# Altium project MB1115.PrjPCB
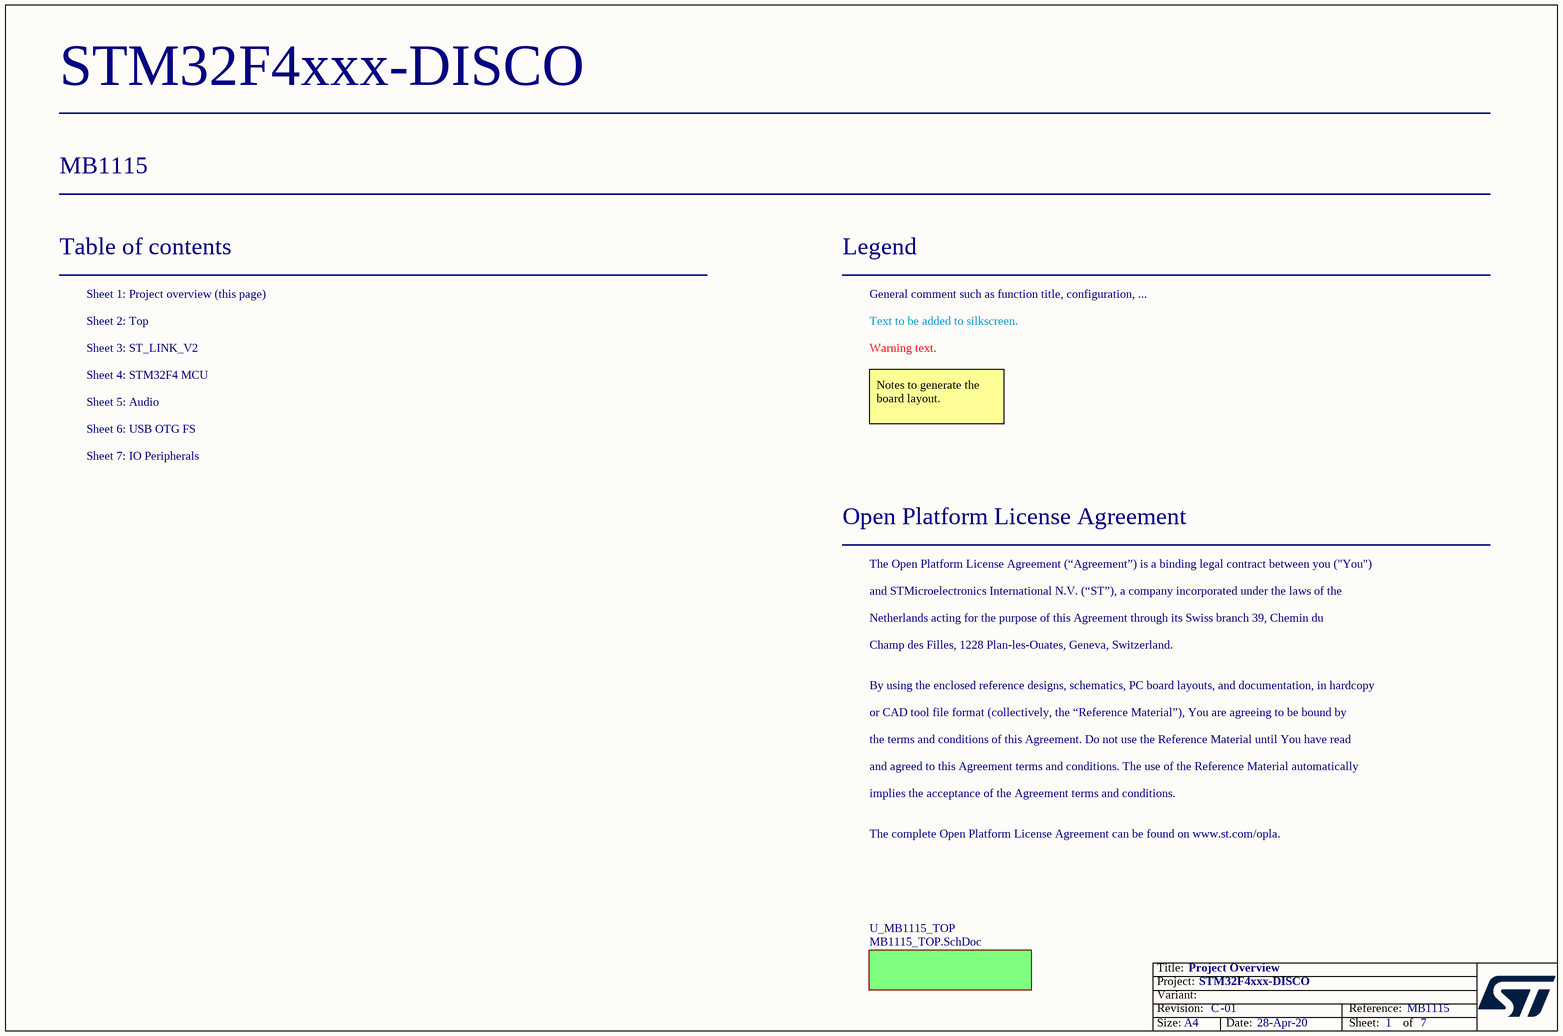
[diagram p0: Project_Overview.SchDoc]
Board_Reference: MB1115; Board_PCB_Revision: C; Board_Name: STM32F4xxx-DISCO; Board_Document_Date: 28-Apr-20; Board_Assembly_Revision: 01
7 sheets, 197 parts. Net scope: flat (ports and power ports of the same name join across sheets).
Board file: MB1115C.PcbDoc
Sheets:
  Project_Overview.SchDoc
    U_MB1115_TOP = MB1115_TOP.SchDoc
      U_ST_LINK = ST_LINK_V2.SCHDOC
      U_Audio = Audio.SchDoc
      U_IO Peripherals = IO Peripherals.SchDoc
      U_STM32Fx = STM32Fx.SchDoc
      U_USB_OTG_FS = USB_OTG_FS.SchDoc

## Sheet Project_Overview.SchDoc: Project Overview
size A4; Date: Not used; ApprovedBy: Not used; CheckedBy: Not used; Author: Not used; CompanyName: STMicroelectronics; DrawnBy: Not used; Engineer: Not used; Organization: Not used; Address1: Not used; Address2: Not used; Address3: Not used; Address4: Not used; DocumentNumber: Not used; Revision: Not used; SheetNumber: 1; SheetTotal: 7

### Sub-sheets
U_MB1115_TOP = MB1115_TOP.SchDoc: no entries

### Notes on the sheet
- Table of contents
- Sheet 1: Project overview (this page)
- Legend
- General comment such as function title, configuration, ...
- Sheet 2: Top
- Sheet 3: ST_LINK_V2
- Sheet 4: STM32F4 MCU
- Text to be added to silkscreen.
- Warning text.
- Sheet 6: USB OTG FS
- Sheet 5: Audio
- Notes to generate the board layout.
- Sheet 7: IO Peripherals
- Open Platform License Agreement
- The Open Platform License Agreement (“Agreement”) is a binding legal contract between you ("You")
- and STMicroelectronics International N.V. (“ST”), a company incorporated under the laws of the
- Netherlands acting for the purpose of this Agreement through its Swiss branch 39, Chemin du
- Champ des Filles, 1228 Plan-les-Ouates, Geneva, Switzerland.
- By using the enclosed reference designs, schematics, PC board layouts, and documentation, in hardcopy
- or CAD tool file format (collectively, the “Reference Material”), You are agreeing to be bound by
- the terms and conditions of this Agreement. Do not use the Reference Material until You have read
- and agreed to this Agreement terms and conditions. The use of the Reference Material automatically
- implies the acceptance of the Agreement terms and conditions.
- The complete Open Platform License Agreement can be found on www.st.com/opla.

## Sheet MB1115_TOP.SchDoc: TOP
size A4; DocumentNumber: 1; SheetNumber: 2; SheetTotal: 7; PageSetup: Record=PageOptions¦CenterHorizontal=True¦CenterVertical=True¦PrintScale=1.00¦XCorrection=1.00¦YCorrection=1.00¦PrintKind=1¦BorderSize=5000000¦LeftOffset=0¦BottomOffset=0¦Orientation=2¦PaperLength=1000¦PaperWidth=1000¦Scale=100¦PaperSource=15¦PrintQuality=1200¦MediaType=1¦DitherType=10¦PaperKind=A4¦PrintScaleMode=1
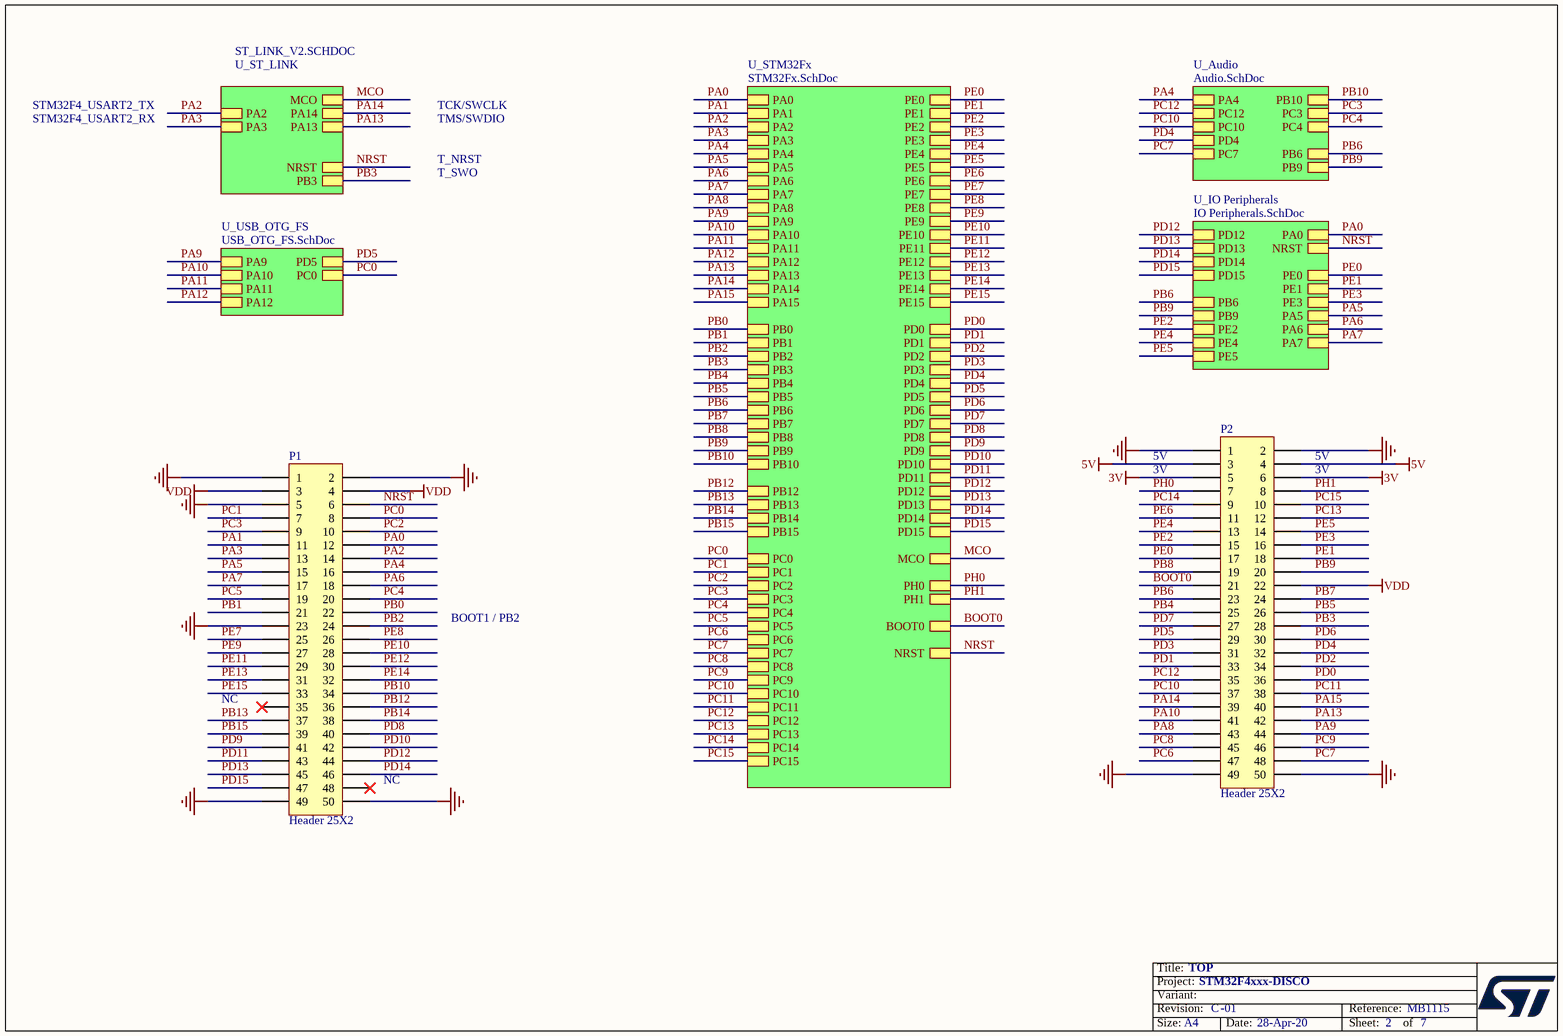
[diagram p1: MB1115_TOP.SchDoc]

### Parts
P1  Header 25X2  [HDR2X25 (Primary)]
P2  Header 25X2  [HDR2X25 (Primary)]

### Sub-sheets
U_Audio = Audio.SchDoc: PA4, PC12, PC10, PD4, PC7, PC3, PB10, PC4, PB6, PB9
U_IO Peripherals = IO Peripherals.SchDoc: PA0, NRST, PE0, PE1, PE3, PA5, PA7, PA6, PE4, PE5, PE2, PB6, PB9, PD12, PD13, PD14, PD15
U_ST_LINK = ST_LINK_V2.SCHDOC: PA13, PA14, NRST, PB3, MCO, PA3, PA2
U_STM32Fx = STM32Fx.SchDoc: PD2, BOOT0, PH1, PH0, NRST, PE0, PE1, PE2, PE3, PE4, PE5, PE6, PE7, PE8, PE9, PE10, PE11, PE12, PE13, PE14, PE15, PD0, PD1, PD3, PD4, PD5, PD6, PD7, PD8, PD9, PD10, PD11, PD12, PD13, PD14, PD15, MCO, PA1, PA2, PA3, PA4, PA5, PA6, PA7, PA8, PA9, PA10, PA11, PA12, PA13, PA14, PA15, PB1, PB2, PB3, PB4, PB5, PB6, PB7, PB8, PB9, PB10, PB12, PB13, PB14, PB15, PC1, PC2, PC3, PC4, PC5, PC6, PC7, PC8, PC9, PC10, PC11, PC12, PC13, PA0, PB0, PC0, PC14, PC15
U_USB_OTG_FS = USB_OTG_FS.SchDoc: PC0, PD5, PA9, PA10, PA11, PA12

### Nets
3V: P2.5 P2.6
5V: P2.3 P2.4
GND: P1.1 P1.2 P1.5 P1.23 P1.49 P1.50 P2.1 P2.2 P2.49 P2.50
VDD: P1.3 P1.4 P2.22
BOOT0: P2.21 ; sheet U_STM32Fx/BOOT0
MCO: sheet U_ST_LINK/MCO, sheet U_STM32Fx/MCO
NRST: P1.6 ; sheet U_ST_LINK/NRST, sheet U_IO Peripherals/NRST, sheet U_STM32Fx/NRST
PA0: P1.12 ; sheet U_IO Peripherals/PA0, sheet U_STM32Fx/PA0
PA1: P1.11 ; sheet U_STM32Fx/PA1
PA2: P1.14 ; sheet U_ST_LINK/PA2, sheet U_STM32Fx/PA2
PA3: P1.13 ; sheet U_ST_LINK/PA3, sheet U_STM32Fx/PA3
PA4: P1.16 ; sheet U_Audio/PA4, sheet U_STM32Fx/PA4
PA5: P1.15 ; sheet U_IO Peripherals/PA5, sheet U_STM32Fx/PA5
PA6: P1.18 ; sheet U_IO Peripherals/PA6, sheet U_STM32Fx/PA6
PA7: P1.17 ; sheet U_IO Peripherals/PA7, sheet U_STM32Fx/PA7
PA8: P2.43 ; sheet U_STM32Fx/PA8
PA9: P2.44 ; sheet U_STM32Fx/PA9, sheet U_USB_OTG_FS/PA9
PA10: P2.41 ; sheet U_STM32Fx/PA10, sheet U_USB_OTG_FS/PA10
PA11: sheet U_STM32Fx/PA11, sheet U_USB_OTG_FS/PA11
PA12: sheet U_STM32Fx/PA12, sheet U_USB_OTG_FS/PA12
PA13: P2.42 ; sheet U_ST_LINK/PA13, sheet U_STM32Fx/PA13
PA14: P2.39 ; sheet U_ST_LINK/PA14, sheet U_STM32Fx/PA14
PA15: P2.40 ; sheet U_STM32Fx/PA15
PB0: P1.22 ; sheet U_STM32Fx/PB0
PB1: P1.21 ; sheet U_STM32Fx/PB1
PB2: P1.24 ; sheet U_STM32Fx/PB2
PB3: P2.28 ; sheet U_ST_LINK/PB3, sheet U_STM32Fx/PB3
PB4: P2.25 ; sheet U_STM32Fx/PB4
PB5: P2.26 ; sheet U_STM32Fx/PB5
PB6: P2.23 ; sheet U_Audio/PB6, sheet U_IO Peripherals/PB6, sheet U_STM32Fx/PB6
PB7: P2.24 ; sheet U_STM32Fx/PB7
PB8: P2.19 ; sheet U_STM32Fx/PB8
PB9: P2.20 ; sheet U_Audio/PB9, sheet U_IO Peripherals/PB9, sheet U_STM32Fx/PB9
PB10: P1.34 ; sheet U_Audio/PB10, sheet U_STM32Fx/PB10
PB12: P1.36 ; sheet U_STM32Fx/PB12
PB13: P1.37 ; sheet U_STM32Fx/PB13
PB14: P1.38 ; sheet U_STM32Fx/PB14
PB15: P1.39 ; sheet U_STM32Fx/PB15
PC0: P1.8 ; sheet U_STM32Fx/PC0, sheet U_USB_OTG_FS/PC0
PC1: P1.7 ; sheet U_STM32Fx/PC1
PC2: P1.10 ; sheet U_STM32Fx/PC2
PC3: P1.9 ; sheet U_Audio/PC3, sheet U_STM32Fx/PC3
PC4: P1.20 ; sheet U_Audio/PC4, sheet U_STM32Fx/PC4
PC5: P1.19 ; sheet U_STM32Fx/PC5
PC6: P2.47 ; sheet U_STM32Fx/PC6
PC7: P2.48 ; sheet U_Audio/PC7, sheet U_STM32Fx/PC7
PC8: P2.45 ; sheet U_STM32Fx/PC8
PC9: P2.46 ; sheet U_STM32Fx/PC9
PC10: P2.37 ; sheet U_Audio/PC10, sheet U_STM32Fx/PC10
PC11: P2.38 ; sheet U_STM32Fx/PC11
PC12: P2.35 ; sheet U_Audio/PC12, sheet U_STM32Fx/PC12
PC13: P2.12 ; sheet U_STM32Fx/PC13
PC14: P2.9 ; sheet U_STM32Fx/PC14
PC15: P2.10 ; sheet U_STM32Fx/PC15
PD0: P2.36 ; sheet U_STM32Fx/PD0
PD1: P2.33 ; sheet U_STM32Fx/PD1
PD2: P2.34 ; sheet U_STM32Fx/PD2
PD3: P2.31 ; sheet U_STM32Fx/PD3
PD4: P2.32 ; sheet U_Audio/PD4, sheet U_STM32Fx/PD4
PD5: P2.29 ; sheet U_STM32Fx/PD5, sheet U_USB_OTG_FS/PD5
PD6: P2.30 ; sheet U_STM32Fx/PD6
PD7: P2.27 ; sheet U_STM32Fx/PD7
PD8: P1.40 ; sheet U_STM32Fx/PD8
PD9: P1.41 ; sheet U_STM32Fx/PD9
PD10: P1.42 ; sheet U_STM32Fx/PD10
PD11: P1.43 ; sheet U_STM32Fx/PD11
PD12: P1.44 ; sheet U_IO Peripherals/PD12, sheet U_STM32Fx/PD12
PD13: P1.45 ; sheet U_IO Peripherals/PD13, sheet U_STM32Fx/PD13
PD14: P1.46 ; sheet U_IO Peripherals/PD14, sheet U_STM32Fx/PD14
PD15: P1.47 ; sheet U_IO Peripherals/PD15, sheet U_STM32Fx/PD15
PE0: P2.17 ; sheet U_IO Peripherals/PE0, sheet U_STM32Fx/PE0
PE1: P2.18 ; sheet U_IO Peripherals/PE1, sheet U_STM32Fx/PE1
PE2: P2.15 ; sheet U_IO Peripherals/PE2, sheet U_STM32Fx/PE2
PE3: P2.16 ; sheet U_IO Peripherals/PE3, sheet U_STM32Fx/PE3
PE4: P2.13 ; sheet U_IO Peripherals/PE4, sheet U_STM32Fx/PE4
PE5: P2.14 ; sheet U_IO Peripherals/PE5, sheet U_STM32Fx/PE5
PE6: P2.11 ; sheet U_STM32Fx/PE6
PE7: P1.25 ; sheet U_STM32Fx/PE7
PE8: P1.26 ; sheet U_STM32Fx/PE8
PE9: P1.27 ; sheet U_STM32Fx/PE9
PE10: P1.28 ; sheet U_STM32Fx/PE10
PE11: P1.29 ; sheet U_STM32Fx/PE11
PE12: P1.30 ; sheet U_STM32Fx/PE12
PE13: P1.31 ; sheet U_STM32Fx/PE13
PE14: P1.32 ; sheet U_STM32Fx/PE14
PE15: P1.33 ; sheet U_STM32Fx/PE15
PH0: P2.7 ; sheet U_STM32Fx/PH0
PH1: P2.8 ; sheet U_STM32Fx/PH1

Not connected (* = marked no-connect by the designer): P1 35* 48*

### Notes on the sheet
- STM32F4_USART2_TX
- TCK/SWCLK
- STM32F4_USART2_RX
- TMS/SWDIO
- T_SWO
- T_NRST
- 5V
- 3V
- (near P2) 5V
- (near P2) 3V
- BOOT1 / PB2
- NC
- (near P1) NC

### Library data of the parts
P1 P2 = Header 25X2: Header, 25-Pin, Dual row

## Sheet ST_LINK_V2.SCHDOC: ST-LINK/V2 (SWD only)
size A4; DocumentNumber: 2; SheetNumber: 3; SheetTotal: 7
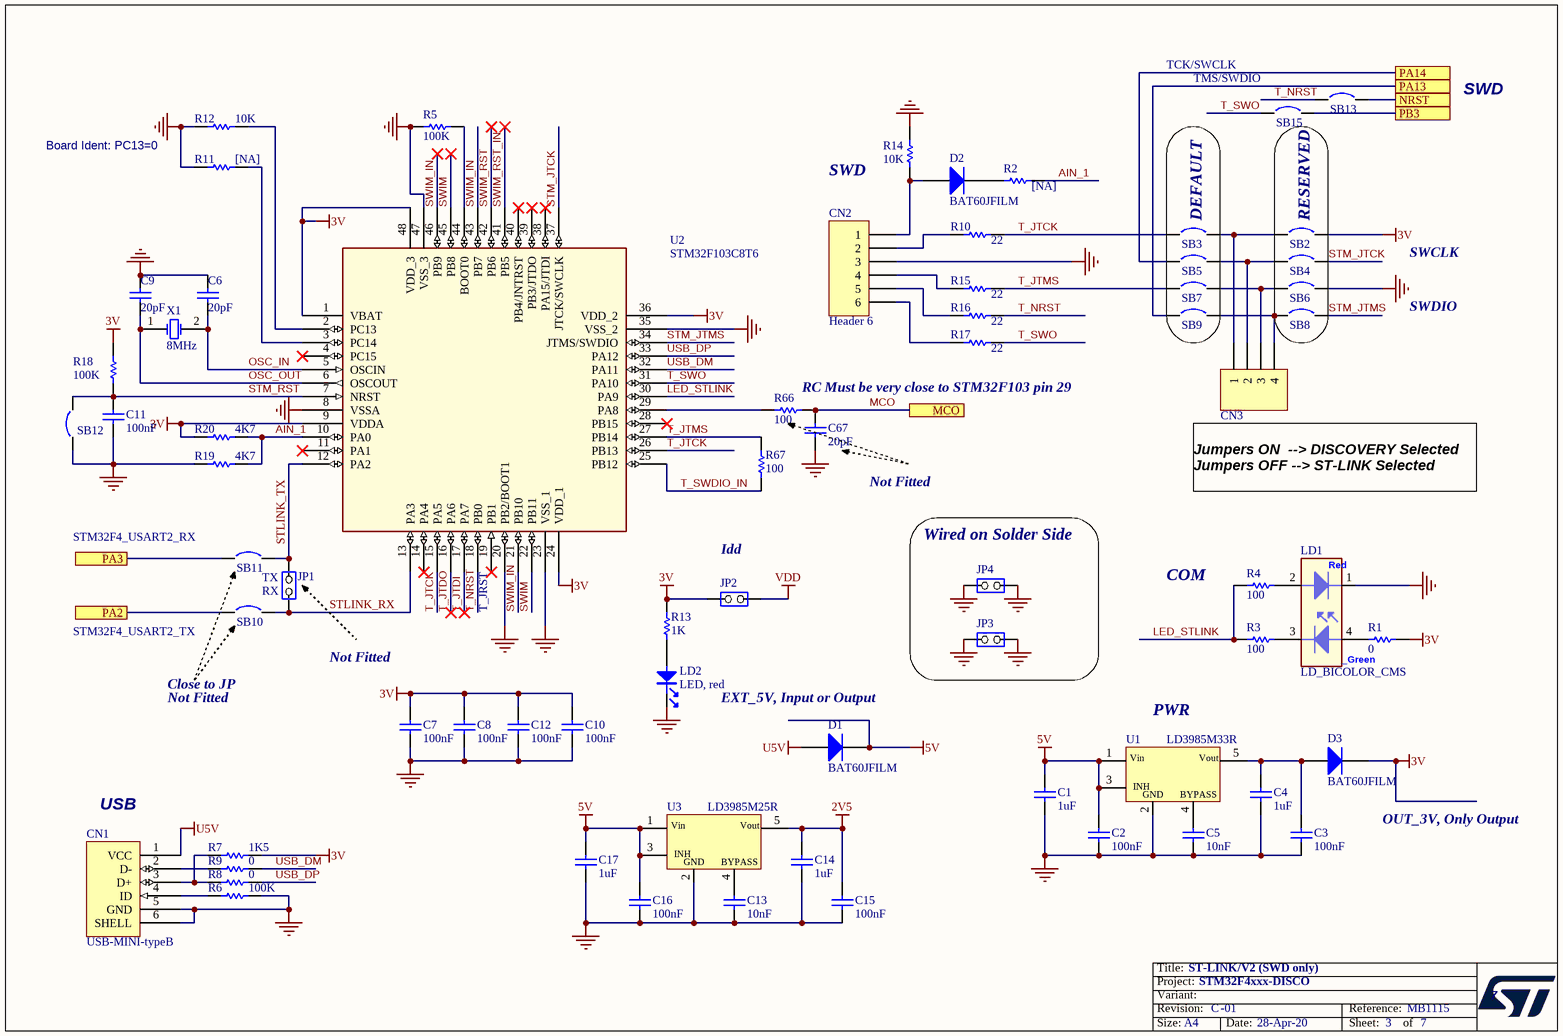
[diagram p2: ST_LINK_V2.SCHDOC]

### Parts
C1  1uF  [0603C (Primary)]
C2  100nF  [0402C (Primary)]
C3  100nF  [0402C (Primary)]
C4  1uF  [0603C (Primary)]
C5  10nF  [0603C (Primary)]
C6  20pF  [0402C (Primary)]
C7  100nF  [0402C (Primary)]
C8  100nF  [0402C (Primary)]
C9  20pF  [0402C (Primary)]
C10  100nF  [0402C (Primary)]
C11  100nF  [0402C (Primary)]
C12  100nF  [0402C (Primary)]
C13  10nF  [0603C (Primary)]
C14  1uF  [0603C (Primary)]
C15  100nF  [0402C (Primary)]
C16  100nF  [0402C (Primary)]
C17  1uF  [0603C (Primary)]
C67  20pF  [0402C (Primary)]
CN1  USB-MINI-typeB  [USB-MINI-B-SMD (Primary)]
CN2  Header 6  [HDR1X6 (Primary)]
CN3  Header 4  [Header 4 (Primary)]  (value not drawn)
D1  BAT60JFILM  [SOD323/A (Primary)]
D2  BAT60JFILM  [SOD323/A (Primary)]
D3  BAT60JFILM  [SOD323/A (Primary)]
JP1  JP2  [SIP2/2.54 (Primary)]  (value not drawn)
JP2  (no value)  [SIP2/2.54 (Primary)]
JP3  (no value)  [SIP2/2.54 (Primary)]
JP4  (no value)  [SIP2/2.54 (Primary)]
LD1  LD_BICOLOR_CMS  [HSMF-A201 (Primary)]
LD2  LED, red  [0603D (Primary)]
R1  0  [0402R (Primary)]
R2  [NA]  [0402R (Primary)]
R3  100  [0402R (Primary)]
R4  100  [0402R (Primary)]
R5  100K  [0402R (Primary)]
R6  100K  [0402R (Primary)]
R7  1K5  [0402R (Primary)]
R8  0  [0402R (Primary)]
R9  0  [0402R (Primary)]
R10  22  [0402R (Primary)]
R11  [NA]  [0402R (Primary)]
R12  10K  [0402R (Primary)]
R13  1K  [0402R (Primary)]
R14  10K  [0402R (Primary)]
R15  22  [0402R (Primary)]
R16  22  [0402R (Primary)]
R17  22  [0402R (Primary)]
R18  100K  [0402R (Primary)]
R19  4K7  [0402R (Primary)]
R20  4K7  [0402R (Primary)]
R66  100  [0402R (Primary)]
R67  100  [0402R (Primary)]
SB2  Circuit Breaker  [JP2_SMD (Primary)]  (value not drawn)
SB3  Circuit Breaker  [JP2_SMD (Primary)]  (value not drawn)
SB4  Circuit Breaker  [JP2_SMD (Primary)]  (value not drawn)
SB5  Circuit Breaker  [JP2_SMD (Primary)]  (value not drawn)
SB6  Circuit Breaker  [JP2_SMD (Primary)]  (value not drawn)
SB7  Circuit Breaker  [JP2_SMD (Primary)]  (value not drawn)
SB8  Circuit Breaker  [JP2_SMD (Primary)]  (value not drawn)
SB9  Circuit Breaker  [JP2_SMD (Primary)]  (value not drawn)
SB10  Circuit Breaker  [JP2_SMD (Primary)]  (value not drawn)
SB11  Circuit Breaker  [JP2_SMD (Primary)]  (value not drawn)
SB12  Circuit Breaker  [JP2_SMD (Primary)]  (value not drawn)
SB13  Circuit Breaker  [JP2_SMD (Primary)]  (value not drawn)
SB15  Circuit Breaker  [JP2_SMD (Primary)]  (value not drawn)
U1  LD3985M33R  [SOT-23-5L (Primary)]
U2  STM32F103C8T6  [LQFP48 (Primary)]
U3  LD3985M25R  [SOT-23-5L (Primary)]
X1  8MHz  [XTAL1 (Primary)]

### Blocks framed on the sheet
DEFAULT: SB3 SB5 SB7 SB9
RESERVED: SB2 SB4 SB6 SB8
Wired on Solder Side: JP3 JP4

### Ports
MCO, NRST, PA2, PA3, PA13, PA14, PB3

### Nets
2V5: C14.1 C15.2 U3.5(Vout)
3V: C7.2 C8.2 C10.2 C12.1 D3.2(K) JP2.1(COMMON) R1.2 R7.2 R13.2 R18.2 R20.1 SB2.2 U2.1(VBAT) U2.9(VDDA) U2.24(VDD_1) U2.36(VDD_2) U2.48(VDD_3)
5V: C1.2 C2.2 C16.2 C17.2 D1.2(K) U1.1(Vin) U1.3(CE) U3.1(Vin) U3.3(CE)
GND: C1.1 C2.1 C3.1 C4.2 C5.1 C6.1 C7.1 C8.1 C9.1 C10.1 C11.1 C12.2 C13.1 C14.2 C15.1 C16.1 C17.1 C67.2 CN1.5(GND) CN1.6(SHELL) CN2.3 JP3.1(COMMON) JP3.2(NO) JP4.1(COMMON) JP4.2(NO) LD1.1 LD2.2 R5.1 R6.2 R11.1 R12.1 R14.2 R19.1 SB6.2 SB12.1 U1.2(GND) U2.8(VSSA) U2.20(PB2/BOOT1) U2.23(VSS_1) U2.35(VSS_2) U2.47(VSS_3) U3.2(GND)
U5V: CN1.1(VCC) D1.1(A)
VDD: JP2.2(NO)
AIN_1: R2.2 R19.2 R20.2 U2.10(PA0)
LED_STLINK: R3.1 R4.1 U2.30(PA9)
MCO: C67.1 R66.2 ; port MCO
NRST: SB13.2 ; port NRST
OSC_IN: C6.2 U2.5(OSCIN) X1.2(OSC2)
OSC_OUT: C9.2 U2.6(OSCOUT) X1.1(OSC1)
PA2: SB10.1 ; port PA2
PA3: SB11.1 ; port PA3
PA13: SB9.1 ; port PA13
PA14: SB5.1 ; port PA14
PB3: SB15.2 ; port PB3
STLINK_RX: JP1.1(COMMON) SB10.2 U2.13(PA3)
STLINK_TX: JP1.2(NO) SB11.2 U2.12(PA2)
STM_JTCK: SB4.2 U2.37(JTCK/SWCLK)
STM_JTMS: SB8.2 U2.34(JTMS/SWDIO)
STM_RST: C11.2 R18.1 SB12.2 U2.7(NRST)
SWIM: U2.22(PB11) U2.45(PB8)
SWIM_IN: U2.21(PB10) U2.43(PB7) U2.46(PB9)
SWIM_RST: U2.42(PB6)
SWIM_RST_IN: U2.41(PB5)
T_JTCK: R10.2 SB3.1 U2.15(PA5) U2.26(PB13)
T_JTDI: U2.17(PA7)
T_JTDO: U2.16(PA6)
T_JTMS: R15.2 R67.2 SB7.1 U2.27(PB14)
T_NRST: R16.2 SB13.1 U2.18(PB0)
T_SWDIO_IN: R67.1 U2.25(PB12)
T_SWO: R17.2 SB15.1 U2.31(PA10)
USB_DM: R9.2 U2.32(PA11)
USB_DP: R8.2 U2.33(PA12)
NetC3_2: C3.2 C4.1 D3.1(A) U1.5(Vout)
NetC5_2: C5.2 U1.4(BYPASS)
NetC13_2: C13.2 U3.4(BYPASS)
NetCN1_2: CN1.2(D-) R9.1
NetCN1_3: CN1.3(D+) R7.1 R8.1
NetCN1_4: CN1.4(ID) R6.1
NetCN2_1: CN2.1 D2.1(A) R14.1
NetCN2_2: CN2.2 R10.1
NetCN2_4: CN2.4 R15.1
NetCN2_5: CN2.5 R16.1
NetCN2_6: CN2.6 R17.1
NetCN3_1: CN3.1 SB2.1 SB3.2
NetCN3_2: CN3.2 SB4.1 SB5.2
NetCN3_3: CN3.3 SB6.1 SB7.2
NetCN3_4: CN3.4 SB8.1 SB9.2
NetD2_2: D2.2(K) R2.1
NetLD1_2: LD1.2 R4.2
NetLD1_3: LD1.3 R3.2
NetLD1_4: LD1.4 R1.1
NetLD2_1: LD2.1 R13.1
NetR5_2: R5.2 U2.44(BOOT0)
NetR11_2: R11.2 U2.3(PC14)
NetR12_2: R12.2 U2.2(PC13)
NetR66_1: R66.1 U2.29(PA8)

Not connected (* = marked no-connect by the designer): U2 4(PC15)* 11(PA1)* 14(PA4)* 19(PB1)* 28(PB15)* 38(PA15/JTDI)* 39(PB3/JTDO)* 40(PB4/JNTRST)*

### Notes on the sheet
- TCK/SWCLK
- (near SB15) TMS/SWDIO
- SWD
- Board Ident: PC13=0
- SWCLK
- SWDIO
- (near R66) RC Must be very close to STM32F103 pin 29
- Not Fitted
- Jumpers ON  --> DISCOVERY Selected
  Jumpers OFF --> ST-LINK Selected
- STM32F4_USART2_RX
- TX
- (near JP2) Idd
- COM
- STM32F4_USART2_TX
- RX
- (near U2) T_JRST
- Close to JP
- EXT_5V, Input or Output
- (near U1) PWR
- (near CN1) USB
- OUT_3V, Only Output

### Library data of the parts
C1 C4 C14 C17 = Cap_1uF_X5R_10%_0603: Capacitor,1uF,16V,X5R,10%,0603,YAGEO; Manuf_Part_1: CC0603KRX5R7BB105
C2 C3 C7 C8 C10-C12 C15 C16 = Cap_100nF_X7R_10%_0402: Capacitor,100nF,16V,X7R,10%,0402,YAGEO; Manuf_Part_1: CC0402KRX7R7BB104
C5 C13 = Cap_10nF_X7R_10%_0603: Capacitor,10nF,50V,X7R,10%,0603,YAGEO; Manuf_Part_1: CC0603KRX7R9BB103
C6 C9 = Cap_20pF_NPO_5%_0402: Capacitor,20pF,50V,NPO,5%,0402,YAGEO; Order: CC0402JRNPO9BN200
C67 = Cap_20pF_NPO_5%_0402: Capacitor,20pF,50V,NPO,5%,0402,YAGEO; Order: CC0402JRNPO9BN200; Fitted: NO
CN1 = USB-MINI-typeB connector: Manuf_Part_1: 5075BMR-05-SM; Manuf_Part_2: 218205M1110T; Manuf_2: lyconn
CN2 = Header 6: Header, 6-Pin
CN3 = Header 4: Header, 4-Pin
D1-D3 = BAT60JFILM: Manuf_1: STM; Provided: ST; ECCN_US/EU: EAR99/NEC; Ref St: 9151097
JP1 = JP2: Fitted: NO
JP2-JP4 = JP2
LD1 = LD_BICOLOR_CMS: Bicolor Led; Manuf_Part_1: HSMF-A201-A00J1; Manuf_1: Avago Technologies; Manuf_2: everluck; Manuf_Part_2: LE-RGW35280; Ref St: xxxxxx
LD2 = LED_red: LED, red, 0603; Manuf_1: everlight; Manuf_Part_1: 19-213-R6C-AP1Q2B/3T
R1 R8 R9 = Res_0_0402: Resistor,0,0402
R2 R11 = Res_NA_0402: Resistor,[NA],0402; Fitted: NO
R3-R7 R10 R12-R20 R67 = res1: Resistor
R66 = res1: Resistor; Fitted: NO
SB2 SB4 SB6 SB8 SB10-SB12 = Circuit Breaker: Solder: NO
SB3 SB5 SB7 SB9 SB13 SB15 = Circuit Breaker: Solder: YES
U1 = LD3985M33R: Ultra low drop-low noise BiCMOS voltage, regulators low ESR capacitors compatible; Manuf_1: STM; Provided: ST; Ref St: 9176161; ECCN_US/EU: EAR99/NEC
U2 = STM32F103C8T6: Medium-density performance line ARM-based 32-bit MCU with 64KB Flash; Manuf_1: STM; Ref St: 9175981; Provided: ST; ECCN_US/EU: 3A991A2/NEC
U3 = LD3985M25R: Ultra low drop-low noise BiCMOS voltage, regulators low ESR capacitors compatible; Manuf_1: STM; Provided: ST; Ref St: 9176007; ECCN_US/EU: EAR99/NEC
X1 = XTAL_8MHZ_20PPM: Crystal Oscillator,8Mhz,20PF,20PPM,-10-70 degree,DIP,HC-49S; Manuf_Part_1: HC-49S-C20QSA-8.000MHZ

## Sheet Audio.SchDoc: Audio
size A4; DocumentNumber: 4; SheetNumber: 5; SheetTotal: 7
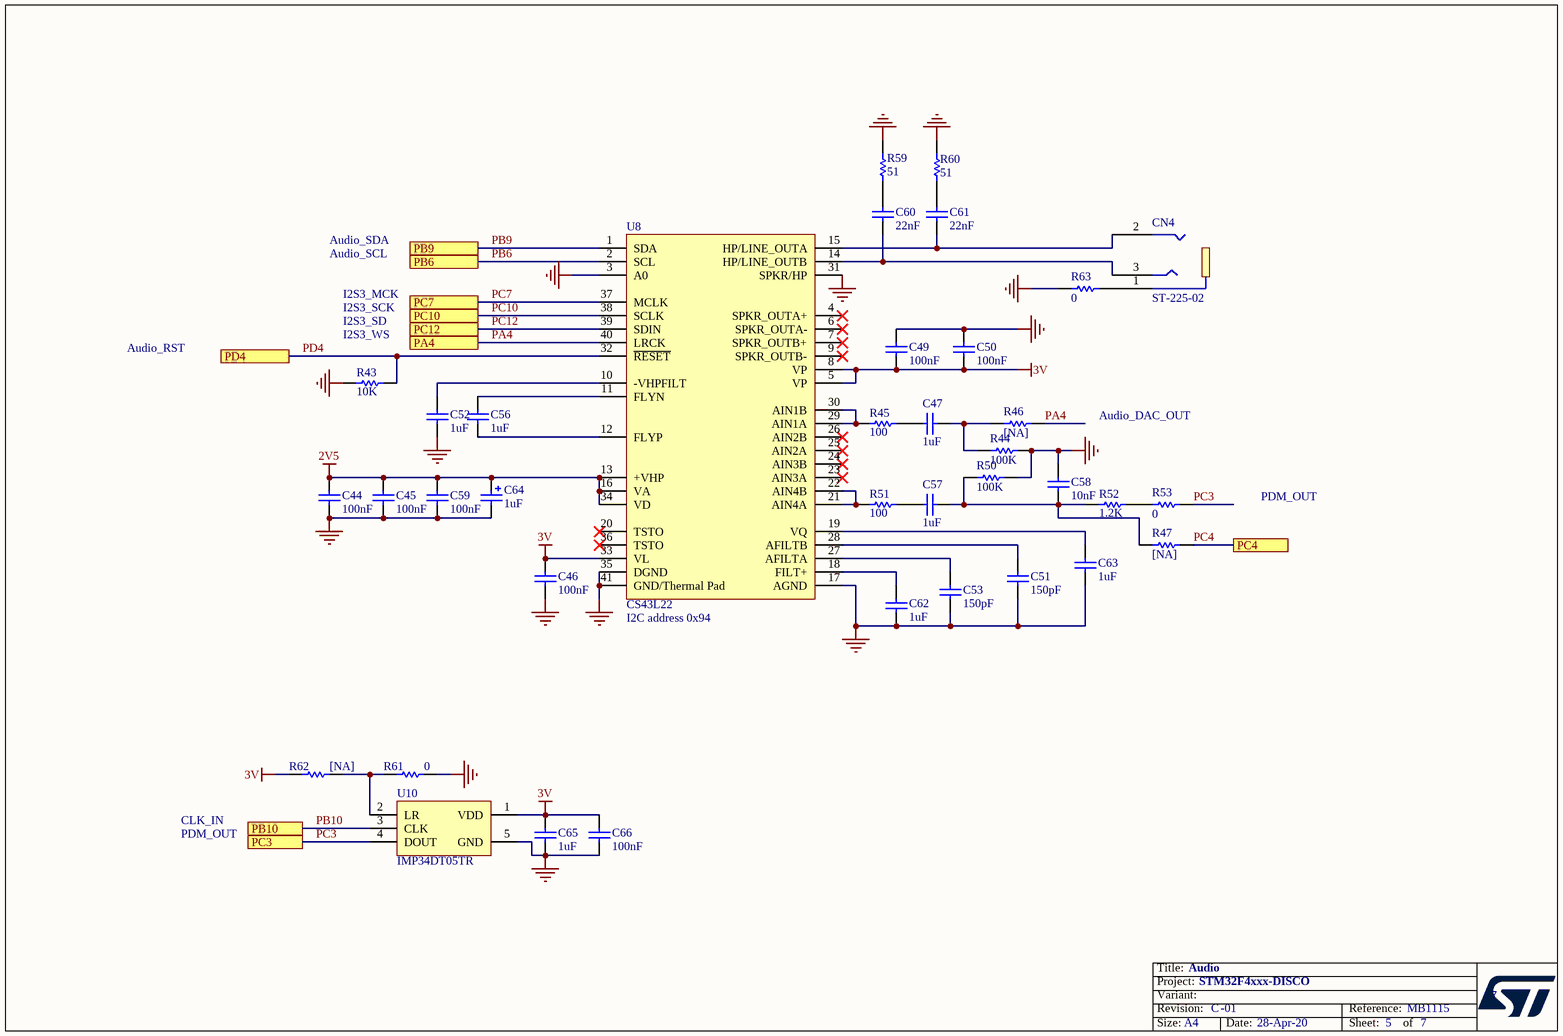
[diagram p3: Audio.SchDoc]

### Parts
C44  100nF  [0402C (Primary)]
C45  100nF  [0402C (Primary)]
C46  100nF  [0402C (Primary)]
C47  1uF  [0603C (Primary)]
C49  100nF  [0402C (Primary)]
C50  100nF  [0402C (Primary)]
C51  150pF  [0603C (Primary)]
C52  1uF  [0603C (Primary)]
C53  150pF  [0603C (Primary)]
C56  1uF  [0603C (Primary)]
C57  1uF  [0603C (Primary)]
C58  10nF  [0603C (Primary)]
C59  100nF  [0402C (Primary)]
C60  22nF  [0603C (Primary)]
C61  22nF  [0603C (Primary)]
C62  1uF  [0603C (Primary)]
C63  1uF  [0603C (Primary)]
C64  1uF  [TAN-A (Primary)]
C65  1uF  [0603C (Primary)]
C66  100nF  [0402C (Primary)]
CN4  ST-225-02  [JACK-ST-225 (Primary)]
R43  10K  [0402R (Primary)]
R44  100K  [0402R (Primary)]
R45  100  [0402R (Primary)]
R46  [NA]  [0402R (Primary)]
R47  [NA]  [0402R (Primary)]
R50  100K  [0402R (Primary)]
R51  100  [0402R (Primary)]
R52  1.2K  [0402R (Primary)]
R53  0  [0402R (Primary)]
R59  51  [0402R (Primary)]
R60  51  [0402R (Primary)]
R61  0  [0402R (Primary)]
R62  [NA]  [0402R (Primary)]
R63  0  [0402R (Primary)]
U8  CS43L22  [QFN40_6X6 (Primary)]
U10  IMP34DT05TR  [MIC_HCLGA_3X4X1_4LD]

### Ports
PA4, PB6, PB9, PB10, PC3, PC4, PC7, PC10, PC12, PD4

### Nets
2V5: C44.2 C45.2 C59.2 C64.1 U8.13(+VHP) U8.16(VA) U8.34(VD)
3V: C46.2 C49.1 C50.2 C65.2 C66.2 R62.2 U8.5(VP) U8.8(VP) U8.33(VL) U10.1(VDD)
GND: C44.1 C45.1 C46.1 C49.2 C50.1 C51.1 C52.2 C53.1 C58.2 C59.1 C62.1 C63.1 C64.2 C65.1 C66.1 R43.2 R44.2 R50.2 R59.2 R60.1 R61.1 R63.1 U8.3(A0) U8.17(AGND) U8.31(SPKR/HP) U8.35(DGND) U8.41(GND/Thermal_Pad) U10.5(GND)
PA4: R46.2 U8.40(LRCK) ; port PA4
PB6: U8.2(SCL) ; port PB6
PB9: U8.1(SDA) ; port PB9
PB10: U10.3(CLK) ; port PB10
PC3: R53.2 U10.4(DOUT) ; port PC3
PC4: R47.2 ; port PC4
PC7: U8.37(MCLK) ; port PC7
PC10: U8.38(SCLK) ; port PC10
PC12: U8.39(SDIN) ; port PC12
PD4: R43.1 U8.32(~{RESET}) ; port PD4
NetC47_1: C47.1 R45.1
NetC47_2: C47.2 R44.1 R46.1
NetC51_2: C51.2 U8.28(AFILTB)
NetC52_1: C52.1 U8.10(-VHPFILT)
NetC53_2: C53.2 U8.27(AFILTA)
NetC56_1: C56.1 U8.12(FLYP)
NetC56_2: C56.2 U8.11(FLYN)
NetC57_1: C57.1 R51.1
NetC57_2: C57.2 C58.1 R47.1 R50.1 R52.1
NetC60_1: C60.1 CN4.3 U8.14(HP/LINE_OUTB)
NetC60_2: C60.2 R59.1
NetC61_1: C61.1 CN4.2 U8.15(HP/LINE_OUTA)
NetC61_2: C61.2 R60.2
NetC62_2: C62.2 U8.18(FILT+)
NetC63_2: C63.2 U8.19(VQ)
NetCN4_1: CN4.1 R63.2
NetR45_2: R45.2 U8.29(AIN1A) U8.30(AIN1B)
NetR51_2: R51.2 U8.21(AIN4A) U8.22(AIN4B)
NetR52_2: R52.2 R53.1
NetR61_2: R61.2 R62.1 U10.2(LR)

Not connected (* = marked no-connect by the designer): U8 4(SPKR_OUTA+)* 6(SPKR_OUTA-)* 7(SPKR_OUTB+)* 9(SPKR_OUTB-)* 20(TSTO)* 23(AIN3A)* 24(AIN3B)* 25(AIN2A)* 26(AIN2B)* 36(TSTO)*

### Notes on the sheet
- Audio_SDA
- Audio_SCL
- I2S3_MCK
- I2S3_SCK
- Audio_RST
- (near R43) I2S3_WS
- I2S3_SD
- Audio_DAC_OUT
- PDM_OUT
- (near U8) I2C address 0x94
- CLK_IN

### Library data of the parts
C44-C46 C49 C50 C59 C66 = Cap_100nF_X7R_10%_0402: as C2 on sheet ST_LINK_V2
C47 C52 C56 C57 C62 C63 C65 = Cap_1uF_X5R_10%_0603: as C1 on sheet ST_LINK_V2
C51 C53 = Cap_150pF_NPO_5%_0603: Capacitor,150pF,50V,NPO,5%,0603,YAGEO; Order: CC0603JRNPO9BN151
C58 = Cap_10nF_X7R_10%_0603: as C5 on sheet ST_LINK_V2
C60 C61 = Cap_22nF_X7R_10%_0603: Capacitor,22nF,50V,X7R,10%,0603,YAGEO; Manuf_Part_1: CC0603KRX7R9BB223
C64 = Cap_1uF_POL_10%_TANA: Polarized Capacitor,1uF,16V,10%,typeA,AVX; Manuf_Part_1: TAJA105K016R
CN4 = ST-225-02: Connector Jack 35mm; Manuf_1: XIEJIA Electronics
R43-R45 R50 R51 R59 R60 = res1: Resistor; Value: 1K
R46 R47 R62 = Res_NA_0402: Resistor,[NA],0402; Fitted: NO
R52 = res1: Resistor
R53 R61 R63 = Res_0_0402: Resistor,0,0402
U8 = CS43L22: Low Power, Stereo DAC w/Headphone & Speaker Amps; Manuf_1: Cirrus; Order: CS43L22-CNZ
U10 = MCD-01715: MEMS audio sensor omnidirectional digital microphone for industrial applications; Part_Type: IC; Manufacturer: STMICROELECTRONICS; BMS_Part_Number: 9177995; ECCN_US: EAR99; ECCN_EU: NEC; Provided_By: SUBCO with ST control

## Sheet IO Peripherals.SchDoc: Peripherals
size A4; DocumentNumber: 6; SheetNumber: 7; SheetTotal: 7
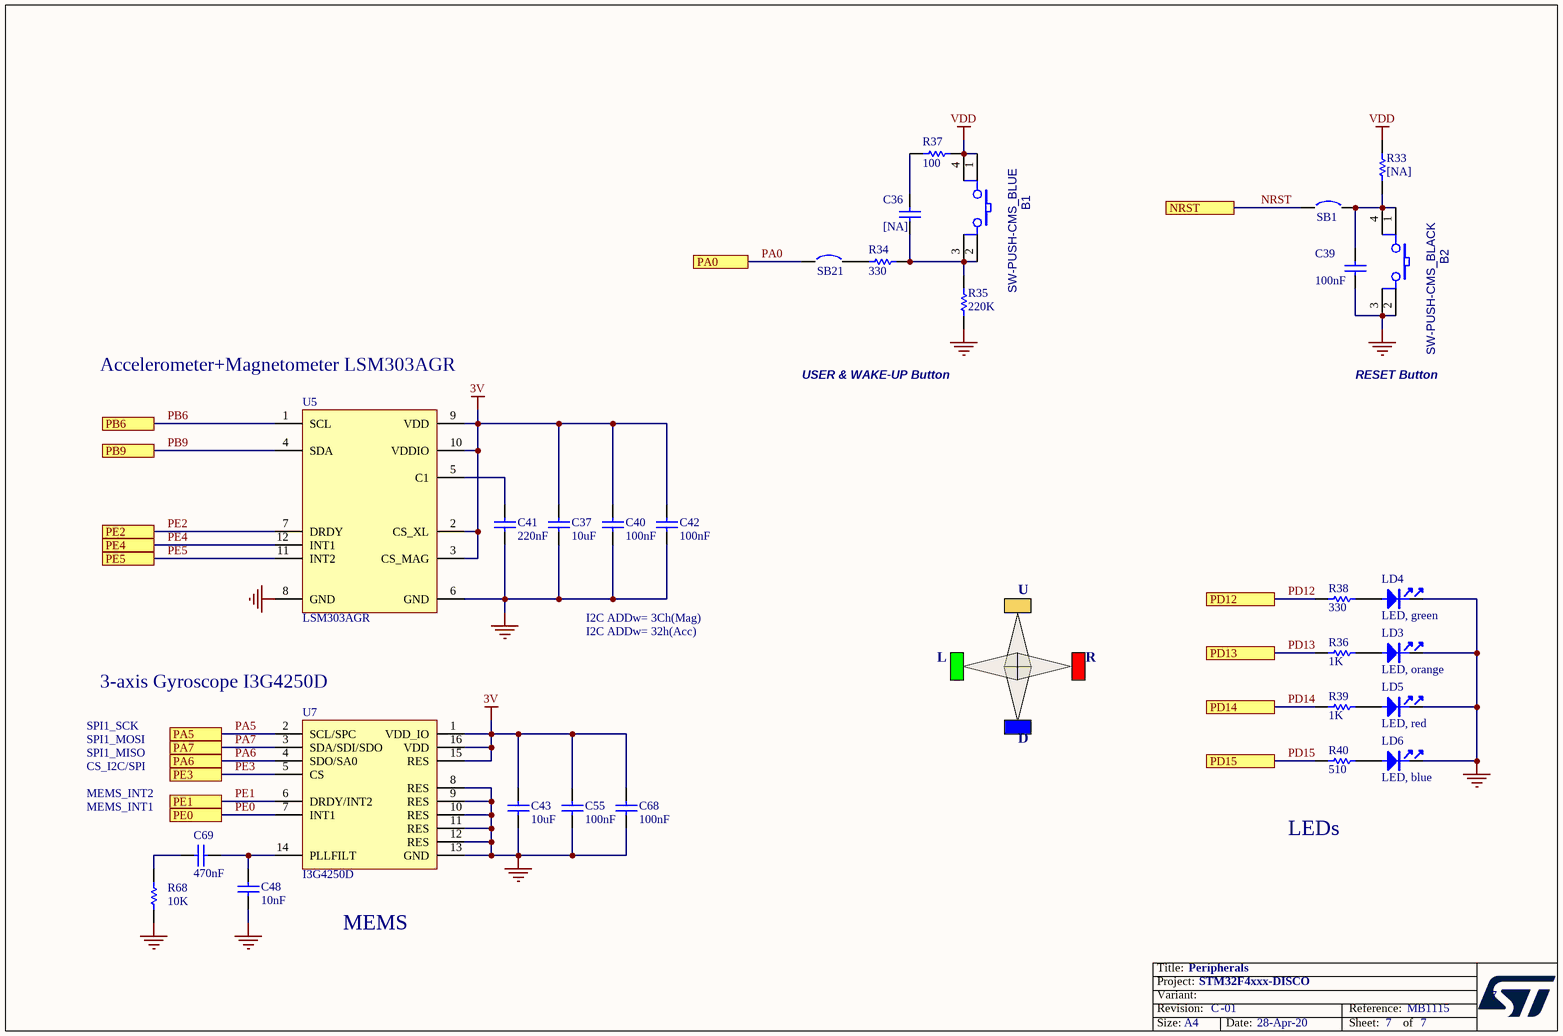
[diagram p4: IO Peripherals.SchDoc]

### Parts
B1  SW-PUSH-CMS_BLUE  [BP1CMS (Primary)]
B2  SW-PUSH-CMS_BLACK  [BP1CMS (Primary)]
C36  [NA]  [0402C (Primary)]
C37  10uF  [0603C (Primary)]
C39  100nF  [0402C (Primary)]
C40  100nF  [0402C (Primary)]
C41  220nF  [0603C (Primary)]
C42  100nF  [0402C (Primary)]
C43  10uF  [0603C (Primary)]
C48  10nF  [0603C (Primary)]
C55  100nF  [0402C (Primary)]
C68  100nF  [0402C (Primary)]
C69  value 470nF  [0603C (Primary)]  (hidden comment: Capacitor)
LD3  LED, orange  [0603D (Primary)]
LD4  LED, green  [0603D (Primary)]
LD5  LED, red  [0603D (Primary)]
LD6  LED, blue  [0603D (Primary)]
R33  [NA]  [0402R (Primary)]
R34  330  [0402R (Primary)]
R35  220K  [0402R (Primary)]
R36  1K  [0402R (Primary)]
R37  100  [0402R (Primary)]
R38  330  [0402R (Primary)]
R39  1K  [0402R (Primary)]
R40  510  [0402R (Primary)]
R68  10K  [0402R (Primary)]
SB1  Circuit Breaker  [JP2_SMD (Primary)]  (value not drawn)
SB21  Circuit Breaker  [JP2_SMD (Primary)]  (value not drawn)
U5  LSM303AGR  [ICC_LGA12_2X2_P050]
U7  I3G4250D  [ICC_LGA16_4X4_P065_H1P1]

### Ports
NRST, PA0, PA5, PA6, PA7, PB6, PB9, PD12, PD13, PD14, PD15, PE0, PE1, PE2, PE3, PE4, PE5

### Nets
3V: C37.2 C40.2 C42.2 C43.2 C55.2 C68.2 U5.2(CS_XL) U5.3(CS_MAG) U5.9(VDD) U5.10(VDDIO) U7.1(VDD_IO) U7.15(RES) U7.16(VDD)
GND: B2.2 B2.3 C37.1 C39.1 C40.1 C41.1 C42.1 C43.1 C48.1 C55.1 C68.1 LD3.2 LD4.2 LD5.2 LD6.2 R35.1 R68.2 U5.6(GND) U5.8(GND) U7.8(RES) U7.9(RES) U7.10(RES) U7.11(RES) U7.12(RES) U7.13(GND)
VDD: B1.1 B1.4 R33.2 R37.2
NRST: SB1.1 ; port NRST
PA0: SB21.1 ; port PA0
PA5: U7.2(SCL/SPC) ; port PA5
PA6: U7.4(SDO/SA0) ; port PA6
PA7: U7.3(SDA/SDI/SDO) ; port PA7
PB6: U5.1(SCL) ; port PB6
PB9: U5.4(SDA) ; port PB9
PD12: R38.2 ; port PD12
PD13: R36.2 ; port PD13
PD14: R39.2 ; port PD14
PD15: R40.2 ; port PD15
PE0: U7.7(INT1) ; port PE0
PE1: U7.6(DRDY/INT2) ; port PE1
PE2: U5.7(DRDY) ; port PE2
PE3: U7.5(CS) ; port PE3
PE4: U5.12(INT1) ; port PE4
PE5: U5.11(INT2) ; port PE5
NetB1_2: B1.2 B1.3 C36.1 R34.2 R35.2
NetB2_1: B2.1 B2.4 C39.2 R33.1 SB1.2
NetC36_2: C36.2 R37.1
NetC41_2: C41.2 U5.5(C1)
NetC48_2: C48.2 C69.1 U7.14(PLLFILT)
NetC69_2: C69.2 R68.1
NetLD3_1: LD3.1 R36.1
NetLD4_1: LD4.1 R38.1
NetLD5_1: LD5.1 R39.1
NetLD6_1: LD6.1 R40.1
NetR34_1: R34.1 SB21.2

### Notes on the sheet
- (near U5) Accelerometer+Magnetometer LSM303AGR
- USER & WAKE-UP Button
- RESET Button
- I2C ADDw= 3Ch(Mag)
- I2C ADDw= 32h(Acc)
- U
- (near U7) 3-axis Gyroscope I3G4250D
- L
- R
- SPI1_MOSI
- SPI1_SCK
- SPI1_MISO
- CS_I2C/SPI
- D
- MEMS_INT1
- MEMS_INT2
- LEDs
- MEMS

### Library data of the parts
B1 = SW-PUSH-CMS_BLUE: Non-Open Push-Button 0.1A 24V; Manuf_2: FARNELL; Manuf_Part_2: 535-930; Manuf_1: wealthmetal; Manuf_Part_1: TD0341X-G01-BLU; Ref St: 9180120
B2 = SW-PUSH-CMS_BLACK: Non-Open Push-Button 0.1A 24V; Manuf_2: FARNELL; Manuf_Part_2: 535-930; Manuf_1: wealthmetal; Manuf_Part_1: TD0341X-G01-BLA; Ref St: 9180120
C36 = Cap_NA_0402: Capacitor,NA,0402; Fitted: NO
C37 C43 = Cap_10uF_X5R_10%_0603: Capacitor,10uF,6.3V,X5R,20%,0603,YAGEO; Manuf_Part_1: CC0603KRX5R5BB106
C39 C40 C42 C55 C68 = Cap_100nF_X7R_10%_0402: as C2 on sheet ST_LINK_V2
C41 = Cap_220nF_X7R_10%_0603: Capacitor,220nF,16V,X7R,10%,0603,YAGEO; Manuf_Part_1: CC0603KRX7R7BB224
C48 = Cap_10nF_X7R_10%_0603: as C5 on sheet ST_LINK_V2
C69 = MCD-01006: Capacitor, MLCC, 470nF, 16V, X7R, 10%, 0603, T=0.8mm; Manufacturer_Part_Number: CC0603KRX7R7BB474; Manufacturer: YAGEO; BMS_Part_Number: 9142003; Provided_By: SUBCO
LD3 = LED_orange: LED, orange, 0603; Manuf_1: everlight; Manuf_Part_1: 19-217/S2C-AM2N2VY/3T
LD4 = LED_green: LED, green, 0603; Manuf_1: everlight; Manuf_Part_1: 19-213SYGC/S530-E2/TR8
LD5 = LED_red: as LD2 on sheet ST_LINK_V2
LD6 = LED_blue: LED, blue, 0603; Manuf_1: everlight; Manuf_Part_1: 19-217/BHC-ZL1M2RY/3T
R33 = Res_NA_0402: Resistor,[NA],0402; Fitted: NO
R34 R68 = res1: Resistor
R35 = res1: Resistor; Value: 10K
R36 R39 = Res1: Resistor
R37 = res1: Resistor; Value: 330
R38 R40 = Res1: Resistor; Value: 1K
SB1 SB21 = Circuit Breaker: Solder: YES
U5 = MCD-00709: 3D accelerometer and 3D magnetometer; Part_Type: IC; Manufacturer: STMICROELECTRONICS; BMS_Part_Number: 9177057; ECCN_US: EAR99; ECCN_EU: NEC; Provided_By: SUBCO with ST control
U7 = MCD-01963: MEMS motion sensor: 3-axis digital output gyroscope LG4-16 4x4mm; Part_Type: IC; Manufacturer: STMICROELECTRONICS; Order_Code_RS: 166-1109; ECCN_US: EAR99; ECCN_EU: NEC; Provided_By: SUBCO with ST control

## Sheet STM32Fx.SchDoc: MCU
size A4; DocumentNumber: 3; SheetNumber: 4; SheetTotal: 7
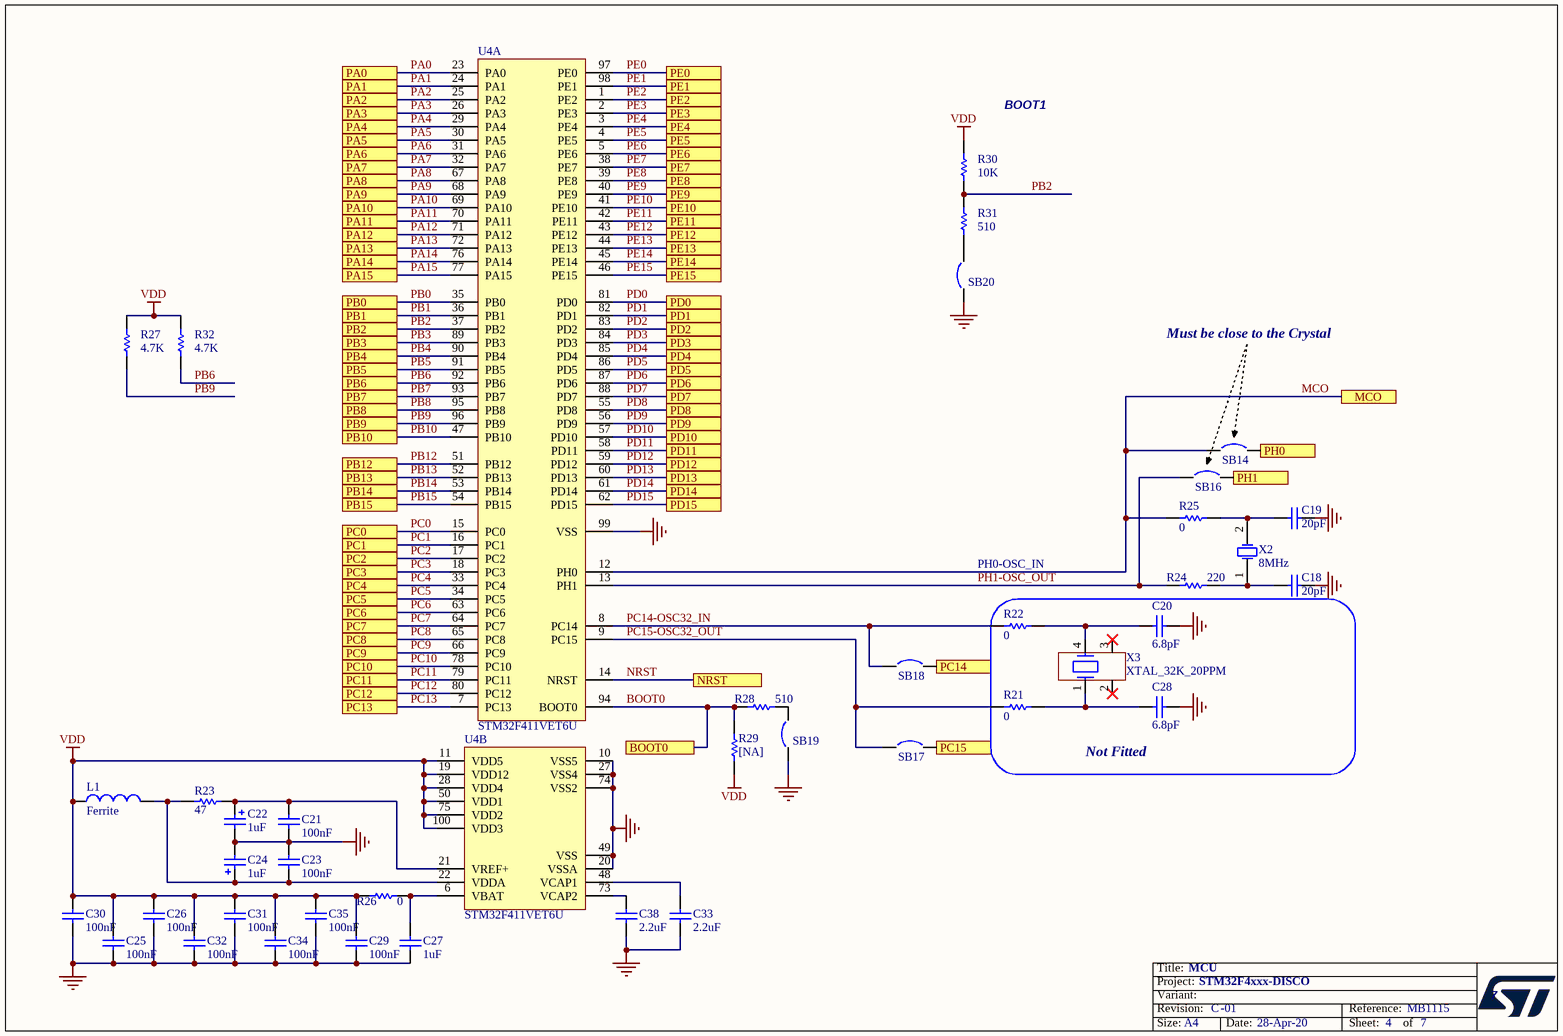
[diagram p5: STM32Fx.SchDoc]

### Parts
C18  20pF  [0402C (Primary)]
C19  20pF  [0402C (Primary)]
C20  6.8pF  [0402C (Primary)]
C21  100nF  [0402C (Primary)]
C22  1uF  [TAN-A (Primary)]
C23  100nF  [0402C (Primary)]
C24  1uF  [TAN-A (Primary)]
C25  100nF  [0402C (Primary)]
C26  100nF  [0402C (Primary)]
C27  1uF  [0603C (Primary)]
C28  6.8pF  [0402C (Primary)]
C29  100nF  [0402C (Primary)]
C30  100nF  [0402C (Primary)]
C31  100nF  [0402C (Primary)]
C32  100nF  [0402C (Primary)]
C33  2.2uF  [TAN-A (Primary)]
C34  100nF  [0402C (Primary)]
C35  100nF  [0402C (Primary)]
C38  2.2uF  [TAN-A (Primary)]
L1  Ferrite  [0603L (Primary)]
R21  0  [0402R (Primary)]
R22  0  [0402R (Primary)]
R23  47  [0402R (Primary)]
R24  220  [0402R (Primary)]
R25  0  [0402R (Primary)]
R26  0  [0402R (Primary)]
R27  4.7K  [0402R (Primary)]
R28  510  [0402R (Primary)]
R29  [NA]  [0402R (Primary)]
R30  10K  [0402R (Primary)]
R31  510  [0402R (Primary)]
R32  4.7K  [0402R (Primary)]
SB14  Circuit Breaker  [JP2_SMD (Primary)]  (value not drawn)
SB16  Circuit Breaker  [JP2_SMD (Primary)]  (value not drawn)
SB17  Circuit Breaker  [JP2_SMD (Primary)]  (value not drawn)
SB18  Circuit Breaker  [JP2_SMD (Primary)]  (value not drawn)
SB19  Circuit Breaker  [JP2_SMD (Primary)]  (value not drawn)
SB20  Circuit Breaker  [JP2_SMD (Primary)]  (value not drawn)
U4  STM32F411VET6U  [TQFP100_14X14 (Primary)]  (parts A,B of 2)
X2  8MHz  [XTAL1 (Primary)]
X3  XTAL_32K_20PPM  [MC306-CRYSTAL (Primary)]

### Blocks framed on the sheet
Not Fitted: C20 C28 R21 R22 X3

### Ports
BOOT0, MCO, NRST, PA0, PA1, PA2, PA3, PA4, PA5, PA6, PA7, PA8, PA9, PA10, PA11, PA12, PA13, PA14, PA15, PB0, PB1, PB2, PB3, PB4, PB5, PB6, PB7, PB8, PB9, PB10, PB12, PB13, PB14, PB15, PC0, PC1, PC2, PC3, PC4, PC5, PC6, PC7, PC8, PC9, PC10, PC11, PC12, PC13, PC14, PC15, PD0, PD1, PD2, PD3, PD4, PD5, PD6, PD7, PD8, PD9, PD10, PD11, PD12, PD13, PD14, PD15, PE0, PE1, PE2, PE3, PE4, PE5, PE6, PE7, PE8, PE9, PE10, PE11, PE12, PE13, PE14, PE15, PH0, PH1

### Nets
GND: C18.1 C19.1 C20.2 C21.1 C22.2 C23.1 C24.2 C25.1 C26.2 C27.2 C28.2 C29.1 C30.1 C31.1 C32.1 C33.2 C34.1 C35.2 C38.2 SB19.1 SB20.1 U4.10(VSS5) U4.20(VSSA) U4.27(VSS4) U4.49(VSS) U4.74(VSS2) U4.99(VSS)
VDD: C25.2 C26.1 C29.2 C30.2 C31.2 C32.2 C34.2 C35.1 L1.1 R26.1 R27.1 R29.1 R30.1 R32.1 U4.11(VDD5) U4.19(VDD12) U4.28(VDD4) U4.50(VDD1) U4.75(VDD2) U4.100(VDD3)
BOOT0: R28.2 R29.2 U4.94(BOOT0) ; port BOOT0
MCO: R25.1 SB14.1 U4.12(PH0) ; port MCO
NRST: U4.14(NRST) ; port NRST
PA0: U4.23(PA0) ; port PA0
PA1: U4.24(PA1) ; port PA1
PA2: U4.25(PA2) ; port PA2
PA3: U4.26(PA3) ; port PA3
PA4: U4.29(PA4) ; port PA4
PA5: U4.30(PA5) ; port PA5
PA6: U4.31(PA6) ; port PA6
PA7: U4.32(PA7) ; port PA7
PA8: U4.67(PA8) ; port PA8
PA9: U4.68(PA9) ; port PA9
PA10: U4.69(PA10) ; port PA10
PA11: U4.70(PA11) ; port PA11
PA12: U4.71(PA12) ; port PA12
PA13: U4.72(PA13) ; port PA13
PA14: U4.76(PA14) ; port PA14
PA15: U4.77(PA15) ; port PA15
PB0: U4.35(PB0) ; port PB0
PB1: U4.36(PB1) ; port PB1
PB2: R30.2 R31.1 U4.37(PB2) ; port PB2
PB3: U4.89(PB3) ; port PB3
PB4: U4.90(PB4) ; port PB4
PB5: U4.91(PB5) ; port PB5
PB6: R32.2 U4.92(PB6) ; port PB6
PB7: U4.93(PB7) ; port PB7
PB8: U4.95(PB8) ; port PB8
PB9: R27.2 U4.96(PB9) ; port PB9
PB10: U4.47(PB10) ; port PB10
PB12: U4.51(PB12) ; port PB12
PB13: U4.52(PB13) ; port PB13
PB14: U4.53(PB14) ; port PB14
PB15: U4.54(PB15) ; port PB15
PC0: U4.15(PC0) ; port PC0
PC1: U4.16(PC1) ; port PC1
PC2: U4.17(PC2) ; port PC2
PC3: U4.18(PC3) ; port PC3
PC4: U4.33(PC4) ; port PC4
PC5: U4.34(PC5) ; port PC5
PC6: U4.63(PC6) ; port PC6
PC7: U4.64(PC7) ; port PC7
PC8: U4.65(PC8) ; port PC8
PC9: U4.66(PC9) ; port PC9
PC10: U4.78(PC10) ; port PC10
PC11: U4.79(PC11) ; port PC11
PC12: U4.80(PC12) ; port PC12
PC13: U4.7(PC13) ; port PC13
PC14-OSC32_IN: R22.1 SB18.1 U4.8(PC14)
PC15-OSC32_OUT: R21.1 SB17.1 U4.9(PC15)
PD0: U4.81(PD0) ; port PD0
PD1: U4.82(PD1) ; port PD1
PD2: U4.83(PD2) ; port PD2
PD3: U4.84(PD3) ; port PD3
PD4: U4.85(PD4) ; port PD4
PD5: U4.86(PD5) ; port PD5
PD6: U4.87(PD6) ; port PD6
PD7: U4.88(PD7) ; port PD7
PD8: U4.55(PD8) ; port PD8
PD9: U4.56(PD9) ; port PD9
PD10: U4.57(PD10) ; port PD10
PD11: U4.58(PD11) ; port PD11
PD12: U4.59(PD12) ; port PD12
PD13: U4.60(PD13) ; port PD13
PD14: U4.61(PD14) ; port PD14
PD15: U4.62(PD15) ; port PD15
PE0: U4.97(PE0) ; port PE0
PE1: U4.98(PE1) ; port PE1
PE2: U4.1(PE2) ; port PE2
PE3: U4.2(PE3) ; port PE3
PE4: U4.3(PE4) ; port PE4
PE5: U4.4(PE5) ; port PE5
PE6: U4.5(PE6) ; port PE6
PE7: U4.38(PE7) ; port PE7
PE8: U4.39(PE8) ; port PE8
PE9: U4.40(PE9) ; port PE9
PE10: U4.41(PE10) ; port PE10
PE11: U4.42(PE11) ; port PE11
PE12: U4.43(PE12) ; port PE12
PE13: U4.44(PE13) ; port PE13
PE14: U4.45(PE14) ; port PE14
PE15: U4.46(PE15) ; port PE15
PH1-OSC_OUT: R24.2 SB16.1 U4.13(PH1)
NetC18_2: C18.2 R24.1 X2.1(OSC1)
NetC19_2: C19.2 R25.2 X2.2(OSC2)
NetC20_1: C20.1 R22.2 X3.4
NetC21_2: C21.2 C22.1 R23.1 U4.21(VREF+)
NetC23_2: C23.2 C24.1 L1.2 R23.2 U4.22(VDDA)
NetC27_1: C27.1 R26.2 U4.6(VBAT)
NetC28_1: C28.1 R21.2 X3.1
NetC33_1: C33.1 U4.48(VCAP1)
NetC38_1: C38.1 U4.73(VCAP2)
NetR28_1: R28.1 SB19.2
NetR31_2: R31.2 SB20.2
NetSB14_2: SB14.2 ; port PH0
NetSB16_2: SB16.2 ; port PH1
NetSB17_2: SB17.2 ; port PC15
NetSB18_2: SB18.2 ; port PC14

Not connected (* = marked no-connect by the designer): X3 2* 3*

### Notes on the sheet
- BOOT1
- Must be close to the Crystal
- PH0-OSC_IN

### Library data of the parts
C18 C19 = Cap_20pF_NPO_5%_0402: as C6 on sheet ST_LINK_V2
C20 C28 = Cap_6.8pF_NPO_4%_0402: Capacitor,6.8pF,50V,NPO,4%,0402,AVX; Order: 04025A6R8CAT2A; Fitted: NO
C21 C23 C25 C26 C29-C32 C34 C35 = Cap_100nF_X7R_10%_0402: as C2 on sheet ST_LINK_V2
C22 C24 = Cap_1uF_POL_10%_TANA: as C64 on sheet Audio
C27 = Cap_1uF_X5R_10%_0603: as C1 on sheet ST_LINK_V2
C33 C38 = Cap_2.2uF_X7R_10%_0805: Capacitor,2.2uF,16V, X7R,10%,0805,YAGEO; Manuf_Part_1: CC0805KKX7R7BB225
L1 = BEAD_600R_350MA_0603: Bead,600R,350mA,0603,FCM1608KF-601T03,Tai-tech; Manuf_2: TDK; Manuf_Part_2: MPZ1608S300A; Value: 100uH; Comment_1: bead,30R,5A,0603,MPZ1608S300A,TDK
R21 R22 = Res_0_0402: Resistor,0,0402; Fitted: NO
R23 = Res1: Resistor; Value: 1K
R24 R28 = Res1: Resistor
R25 R26 = Res_0_0402: Resistor,0,0402
R27 R32 = res1: Resistor; Value: 10K
R29 = Res_NA_0402: Resistor,[NA],0402; Fitted: NO
R30 R31 = res1: Resistor
SB14 SB16 SB20 = Circuit Breaker: Solder: NO
SB17-SB19 = Circuit Breaker: Solder: YES
U4 = STM32F401VCT6U: STM32 Tiny Manta (STM32F401VCT6U); Manuf_1: STM; Provided: ST; Ref St: 9175846; ECCN_US/EU: 3A991A2/NEC
X2 = XTAL_8MHZ_20PPM: as X1 on sheet ST_LINK_V2
X3 = XTAL_32K: Crystal oscillator for clock,32.768K,6PF,20PPM,-40~85 degree,SMT; Manuf_Part_1: ETMB32.768W060BMPF; Comment_1: MC306-G-06Q-32.768; Fitted: NO

## Sheet USB_OTG_FS.SchDoc: USB_OTG_FS
size A4; DocumentNumber: 5; SheetNumber: 6; SheetTotal: 7
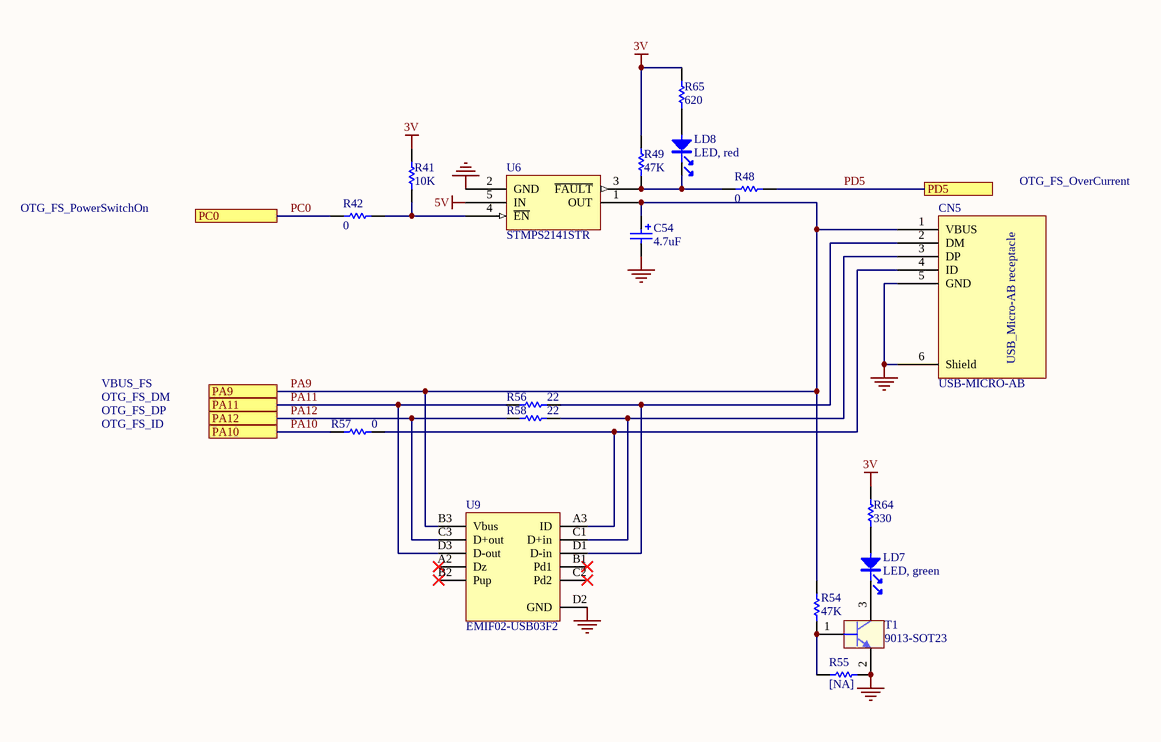
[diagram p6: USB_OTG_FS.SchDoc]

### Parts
C54  4.7uF  [TAN-A (Primary)]
CN5  USB-MICRO-AB  [USB-MICRO-AB (Primary)]
LD7  LED, green  [0603D (Primary)]
LD8  LED, red  [0603D (Primary)]
R41  10K  [0402R (Primary)]
R42  0  [0402R (Primary)]
R48  0  [0402R (Primary)]
R49  47K  [0402R (Primary)]
R54  47K  [0402R (Primary)]
R55  [NA]  [0402R (Primary)]
R56  22  [0402R (Primary)]
R57  0  [0402R (Primary)]
R58  22  [0402R (Primary)]
R64  330  [0603R (Primary)]
R65  620  [0603R (Primary)]
T1  9013-SOT23  [SOT23 (Primary)]
U6  STMPS2141STR  [SOT23-5L (Primary)]
U9  EMIF02-USB03F2  [Flip Chip (Primary)]

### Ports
PA9, PA10, PA11, PA12, PC0, PD5

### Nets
3V: R41.1 R49.1 R64.2 R65.2
5V: U6.5(IN)
GND: C54.2 CN5.5(GND) CN5.6(Shield) R55.2 T1.2(E) U6.2(GND) U9.D2(GND)
PA9: C54.1 CN5.1(VBUS) R54.2 U6.1(OUT) U9.B3(Vbus) ; port PA9
PA10: R57.1 ; port PA10
PA11: R56.2 U9.D3(D-out) ; port PA11
PA12: R58.2 U9.C3(D+out) ; port PA12
PC0: R42.1 ; port PC0
PD5: R48.2 ; port PD5
NetCN5_2: CN5.2(DM) R56.1 U9.D1(D-in)
NetCN5_3: CN5.3(DP) R58.1 U9.C1(D+in)
NetCN5_4: CN5.4(ID) R57.2 U9.A3(ID)
NetLD7_1: LD7.1 R64.1
NetLD7_2: LD7.2 T1.3(C)
NetLD8_1: LD8.1 R65.1
NetLD8_2: LD8.2 R48.1 R49.2 U6.3(~{FAULT})
NetR41_2: R41.2 R42.2 U6.4(~{EN})
NetR54_1: R54.1 R55.1 T1.1(B)

Not connected (* = marked no-connect by the designer): U9 A2(Dz)* B1(Pd1)* B2(Pup)* C2(Pd2)*

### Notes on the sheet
- OTG_FS_PowerSwitchOn
- OTG_FS_OverCurrent
- VBUS_FS
- OTG_FS_ID
- OTG_FS_DM
- OTG_FS_DP

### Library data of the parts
C54 = Cap_4.7uF_POL_10%_TANA: Polarized Capacitor,4.7uF,16V,10%,typeA,AVX; Manuf_Part_1: TAJA475K016R
CN5 = USB-MICRO-AB: USB-MICRO-AB, 47590-0001, SMT, MOLEX; Ref St: xxxxxxx
LD7 = LED_green: as LD4 on sheet IO Peripherals
LD8 = LED_red: as LD2 on sheet ST_LINK_V2
R41 R49 R54 R64 = res1: Resistor; Value: 1K
R42 R48 R57 = Res_0_0402: Resistor,0,0402
R55 = Res_NA_0402: Resistor,[NA],0402; Fitted: NO
R56 R58 R65 = Res1: Resistor; Value: 1K
T1 = 9013-SOT23: NPN Bipolar Transistor; Manuf_1: unisonic; Manuf_Part_1: MMBT9013
U6 = STMPS2141STR: Enhanced single channel power switches; Manuf_1: STM; Provided: ST; ECCN_US/EU: EAR99/NEC; Ref St: 9159003
U9 = EMIF02-USB03F2: 2-line IPAD, EMI filter including ESD protection; Manuf_1: STM; Provided: ST; ECCN_US/EU: EAR99/NEC; Ref St: 9179037

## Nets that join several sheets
2V5: ST_LINK_V2 (C14.1 C15.2 U3.5), Audio (7 pins)
3V: MB1115_TOP (P2.5 P2.6), ST_LINK_V2 (17 pins), Audio (10 pins), IO Peripherals (13 pins), USB_OTG_FS (R41.1 R49.1 R64.2 R65.2)
5V: MB1115_TOP (P2.3 P2.4), ST_LINK_V2 (9 pins), USB_OTG_FS (U6.5)
GND: MB1115_TOP (10 pins), ST_LINK_V2 (42 pins), Audio (28 pins), IO Peripherals (25 pins), STM32Fx (27 pins), USB_OTG_FS (7 pins)
VDD: MB1115_TOP (P1.3 P1.4 P2.22), ST_LINK_V2 (JP2.2), IO Peripherals (B1.1 B1.4 R33.2 R37.2), STM32Fx (20 pins)
MCO: ST_LINK_V2 (C67.1 R66.2), STM32Fx (R25.1 SB14.1 U4.12)
NRST: ST_LINK_V2 (SB13.2), IO Peripherals (SB1.1), STM32Fx (U4.14)
PA0: IO Peripherals (SB21.1), STM32Fx (U4.23)
PA2: ST_LINK_V2 (SB10.1), STM32Fx (U4.25)
PA3: ST_LINK_V2 (SB11.1), STM32Fx (U4.26)
PA4: Audio (R46.2 U8.40), STM32Fx (U4.29)
PA5: IO Peripherals (U7.2), STM32Fx (U4.30)
PA6: IO Peripherals (U7.4), STM32Fx (U4.31)
PA7: IO Peripherals (U7.3), STM32Fx (U4.32)
PA9: STM32Fx (U4.68), USB_OTG_FS (5 pins)
PA10: STM32Fx (U4.69), USB_OTG_FS (R57.1)
PA11: STM32Fx (U4.70), USB_OTG_FS (R56.2 U9.D3)
PA12: STM32Fx (U4.71), USB_OTG_FS (R58.2 U9.C3)
PA13: ST_LINK_V2 (SB9.1), STM32Fx (U4.72)
PA14: ST_LINK_V2 (SB5.1), STM32Fx (U4.76)
PB3: ST_LINK_V2 (SB15.2), STM32Fx (U4.89)
PB6: Audio (U8.2), IO Peripherals (U5.1), STM32Fx (R32.2 U4.92)
PB9: Audio (U8.1), IO Peripherals (U5.4), STM32Fx (R27.2 U4.96)
PB10: Audio (U10.3), STM32Fx (U4.47)
PC0: STM32Fx (U4.15), USB_OTG_FS (R42.1)
PC3: Audio (R53.2 U10.4), STM32Fx (U4.18)
PC4: Audio (R47.2), STM32Fx (U4.33)
PC7: Audio (U8.37), STM32Fx (U4.64)
PC10: Audio (U8.38), STM32Fx (U4.78)
PC12: Audio (U8.39), STM32Fx (U4.80)
PD4: Audio (R43.1 U8.32), STM32Fx (U4.85)
PD5: STM32Fx (U4.86), USB_OTG_FS (R48.2)
PD12: IO Peripherals (R38.2), STM32Fx (U4.59)
PD13: IO Peripherals (R36.2), STM32Fx (U4.60)
PD14: IO Peripherals (R39.2), STM32Fx (U4.61)
PD15: IO Peripherals (R40.2), STM32Fx (U4.62)
PE0: IO Peripherals (U7.7), STM32Fx (U4.97)
PE1: IO Peripherals (U7.6), STM32Fx (U4.98)
PE2: IO Peripherals (U5.7), STM32Fx (U4.1)
PE3: IO Peripherals (U7.5), STM32Fx (U4.2)
PE4: IO Peripherals (U5.12), STM32Fx (U4.3)
PE5: IO Peripherals (U5.11), STM32Fx (U4.4)

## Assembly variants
F411VE: not fitted C20 C28 C36 C67 JP1 R2 R11 R21 R22 R29 R33 R46 R47 R55 R62 R66 SB2 SB4 SB6 SB8 SB10 SB11 SB12 SB14 SB16 SB20 X3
